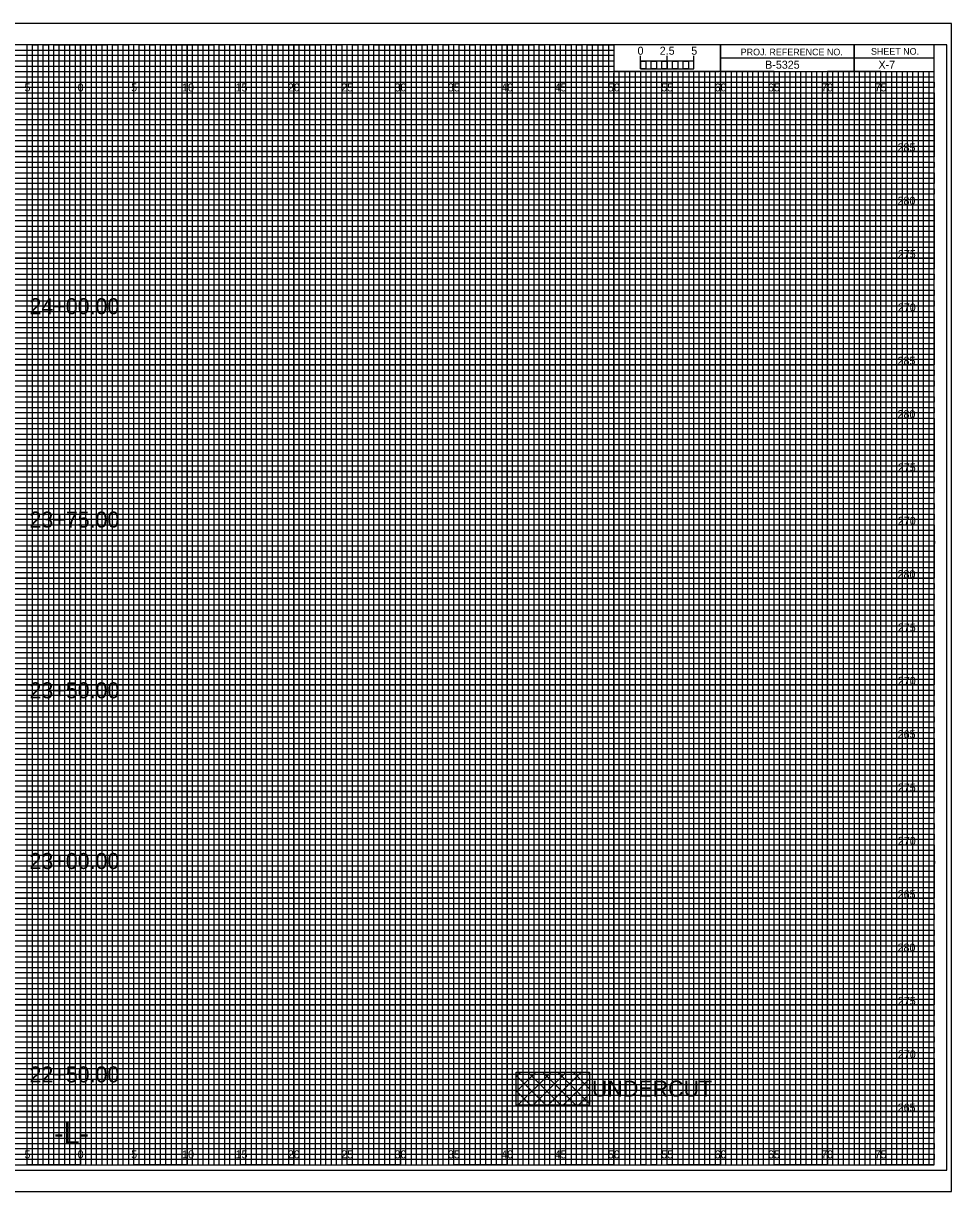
# Model space of a CAD drawing. Extents: x -7 to 162, y 658 to 767.
# Drawn here: x 74.6 to 161.7, y 657.5 to 767 of the extents above; entities that cross this region are included whole.
import ezdxf

# ---------------------------------------------------------------- set-up
doc = ezdxf.new("R2010")
doc.units = 0
for name, color, linetype in [('Default', 7, 'Continuous'), ('Prop XS Alignment Label', 7, 'Continuous'), ('Prop XS Bar Scale Labels', 7, 'Continuous'), ('Prop XS Elevation Labels', 7, 'Continuous'), ('Prop XS Offset Labels', 7, 'Continuous'), ('Prop XS Project Number', 7, 'Continuous'), ('Prop XS Sheet Number', 7, 'Continuous'), ('Prop XS Station Labels', 7, 'Continuous'), ('Sheet Cross Section CELL', 7, 'Continuous'), ('Sheet Cross Section Grid Major CELL', 7, 'Continuous'), ('Sheet Cross Section Grid Middle CELL', 7, 'Continuous'), ('Sheet Cross Section Grid Minor 1 CELL', 7, 'Continuous'), ('Sheet Cross Section Grid Minor 2 CELL', 7, 'Continuous'), ('Sheet Cross Section Scale CELL', 7, 'Continuous'), ('Sheet Cutting Line CELL', 7, 'Continuous'), ('Sheet DOT Grid CELL', 7, 'Continuous'), ('Sheet Plot Border Inside CELL', 7, 'Continuous'), ('Sheet Plot Border Outside CELL', 7, 'Continuous')]:
    doc.layers.add(name, color=color, linetype=linetype)

msp = doc.modelspace()

# ---------------------------------------------------------------- linework, layer by layer
at = {"layer": 'Default'}
for p, q in [((120.83, 668.27), (121.27, 668.7)), ((120.83, 666.85), (122.68, 668.7)), ((120.83, 668.37), (123.6, 665.6)), ((120.99, 665.6), (124.1, 668.7)), ((121.92, 668.7), (125.02, 665.6)), ((122.41, 665.6), (125.51, 668.7)), ((123.33, 668.7), (126.43, 665.6)), ((123.82, 665.6), (126.92, 668.7)), ((124.74, 668.7), (127.72, 665.72)), ((125.24, 665.6), (127.72, 668.08)), ((126.16, 668.7), (127.72, 667.14)), ((127.57, 668.7), (127.72, 668.55)), ((120.83, 666.96), (122.19, 665.6)), ((126.66, 665.6), (127.72, 666.67))]:
    msp.add_line(p, q, dxfattribs=at)
msp.add_lwpolyline([(120.83, 668.7), (127.72, 668.7), (127.72, 665.6), (120.83, 665.6)], close=True, dxfattribs=at)
at = {"layer": 'Sheet Cross Section CELL'}
for p, q in [((152.5, 765), (152.5, 762.5)), ((152.5, 762.5), (152.5, 765)), ((160, 763.75), (140, 763.75)), ((140, 763.75), (140, 762.5)), ((140, 762.5), (160, 762.5))]:
    msp.add_line(p, q, dxfattribs=at)
for points in [[(160, 765), (0, 765), (0, 660), (160, 660)], [(140, 765), (130, 765), (130, 762.51), (140, 762.51)], [(160, 765), (140, 765), (140, 762.5), (160, 762.5)]]:
    msp.add_lwpolyline(points, close=True, dxfattribs=at)
at = {"layer": 'Sheet Cross Section Grid Major CELL'}
for p, q in [((75, 765), (70, 765)), ((75, 660), (75, 765)), ((85, 765), (80, 765)), ((80, 765), (80, 660)), ((85, 660), (85, 765)), ((95, 765), (90, 765)), ((90, 765), (90, 660)), ((95, 660), (95, 765)), ((105, 765), (100, 765)), ((100, 765), (100, 660)), ((105, 660), (105, 765)), ((115, 765), (110, 765)), ((110, 765), (110, 660)), ((115, 660), (115, 765)), ((125, 765), (120, 765)), ((120, 765), (120, 660)), ((125, 660), (125, 765)), ((130, 765), (130, 660)), ((135, 660), (135, 762.5)), ((145, 762.5), (140, 762.5)), ((140, 762.5), (140, 660)), ((145, 660), (145, 762.5)), ((155, 762.5), (150, 762.5)), ((150, 762.5), (150, 660)), ((155, 660), (155, 762.5)), ((80, 660), (75, 660)), ((90, 660), (85, 660)), ((100, 660), (95, 660)), ((110, 660), (105, 660)), ((120, 660), (115, 660)), ((130, 660), (125, 660)), ((140, 660), (135, 660)), ((150, 660), (145, 660)), ((160, 660), (155, 660)), ((160, 660), (160, 660))]:
    msp.add_line(p, q, dxfattribs=at)
for points in [[(0, 760), (160, 760), (160, 755), (0, 755)], [(0, 750), (160, 750), (160, 745), (0, 745)], [(0, 740), (160, 740), (160, 735), (0, 735)], [(0, 730), (160, 730), (160, 725), (0, 725)], [(0, 720), (160, 720), (160, 715), (0, 715)], [(0, 710), (160, 710), (160, 705), (0, 705)], [(0, 700), (160, 700), (160, 695), (0, 695)], [(0, 690), (160, 690), (160, 685), (0, 685)], [(0, 680), (160, 680), (160, 675), (0, 675)], [(0, 670), (160, 670), (160, 665), (0, 665)]]:
    msp.add_lwpolyline(points, dxfattribs=at)
at = {"layer": 'Sheet Cross Section Grid Middle CELL'}
for points in [[(72.5, 660), (77.5, 660), (77.5, 765), (82.5, 765), (82.5, 660), (87.5, 660), (87.5, 765), (92.5, 765), (92.5, 660), (97.5, 660), (97.5, 765), (102.5, 765), (102.5, 660), (107.5, 660), (107.5, 765), (112.5, 765), (112.5, 660), (117.5, 660), (117.5, 765), (122.5, 765), (122.5, 660), (127.5, 660), (127.5, 765), (129.97, 765), (130, 765), (130, 762.5), (132.5, 762.5), (132.5, 660), (137.5, 660), (137.5, 762.5), (142.5, 762.5), (142.5, 660), (147.5, 660), (147.5, 762.5), (152.5, 762.5), (152.5, 660), (157.5, 660), (157.5, 762.5)], [(0, 762.5), (137.5, 762.5)], [(0, 752.5), (160, 752.5), (160, 757.5), (0, 757.5)], [(0, 742.5), (160, 742.5), (160, 747.5), (0, 747.5)], [(0, 732.5), (160, 732.5), (160, 737.5), (0, 737.5)], [(0, 722.5), (160, 722.5), (160, 727.5), (0, 727.5)], [(0, 712.5), (160, 712.5), (160, 717.5), (0, 717.5)], [(0, 702.5), (160, 702.5), (160, 707.5), (0, 707.5)], [(0, 692.5), (160, 692.5), (160, 697.5), (0, 697.5)], [(0, 682.5), (160, 682.5), (160, 687.5), (0, 687.5)], [(0, 672.5), (160, 672.5), (160, 677.5), (0, 677.5)], [(0, 662.5), (160, 662.5), (160, 667.5), (0, 667.5)]]:
    msp.add_lwpolyline(points, dxfattribs=at)
at = {"layer": 'Sheet Cross Section Grid Minor 1 CELL'}
for p, q in [((0, 764.5), (130, 764.5)), ((130, 764.5), (130, 763.99)), ((130, 763.99), (0, 763.99)), ((0, 763.5), (130, 763.5)), ((130, 763.5), (130, 762.95)), ((130, 762.95), (0, 762.95)), ((0, 762), (160, 762))]:
    msp.add_line(p, q, dxfattribs=at)
for points in [[(0, 761.5), (135, 761.5), (160, 761.5), (160, 761), (0, 761)], [(0, 760.5), (160, 760.5), (160, 759.5), (0, 759.5)], [(0, 759), (160, 759), (160, 758.5), (0, 758.49)], [(0, 758), (160, 758), (160, 757), (0, 757)], [(0, 756.5), (160, 756.5), (160, 756), (0, 756)], [(0, 755.5), (160, 755.5), (160, 754.5), (0, 754.5)], [(0, 754), (160, 754), (160, 753.5), (0, 753.5)], [(0, 753), (160, 753), (160, 752), (0, 752)], [(0, 751.5), (160, 751.5), (160, 751), (0, 751)], [(0, 750.5), (160, 750.5), (160, 749.5), (0, 749.5)], [(0, 749), (160, 749), (160, 748.5), (0, 748.5)], [(0, 748), (160, 748), (160, 746.98), (160, 746.5), (160, 746), (0, 746)], [(0, 747), (160, 747), (160, 746.5), (0, 746.5)], [(0, 745.5), (160, 745.5), (160, 744.5), (0, 744.51)], [(0, 744.51), (160, 744.5), (160, 744), (0, 744)], [(0, 743.5), (160, 743.5), (160, 743), (0, 743)], [(0, 742), (160, 742), (160, 741.5), (0, 741.5)], [(0, 741), (160, 741), (160, 740.5), (0, 740.5)], [(-0.04, 739.45), (160, 739.45), (160, 738.94), (-0.04, 738.94)], [(0, 738.5), (160, 738.5), (160, 738), (0, 738)], [(0, 737), (160, 737), (160, 736.5), (0, 736.5)], [(0, 736), (160, 736), (160, 735.5), (0, 735.5)], [(0, 734.5), (160, 734.5), (160, 734), (0, 734)], [(0, 733.5), (160, 733.5), (160, 733), (0, 733)], [(0, 732), (160, 732), (160, 731.5), (0, 731.5)], [(0, 731), (160, 731), (160, 730.5), (0, 730.5)], [(0, 729.5), (160, 729.5), (160, 728.99), (0, 729)], [(0, 728.5), (160, 728.5), (160, 728), (0, 728)], [(0, 727), (160, 727), (160, 726.5), (0, 726.5)], [(0, 726), (160, 726), (160, 725.5), (0, 725.5)], [(0, 724.5), (160, 724.5), (160, 724), (0, 724)], [(0, 723.5), (160, 723.5), (160, 723), (0, 723)], [(0, 722), (160, 722), (160, 721.5), (0, 721.5)], [(0, 721), (160, 721), (160, 720.5), (0, 720.5)], [(0, 719.5), (160, 719.5), (160, 719), (0, 719)], [(0, 718.5), (160.03, 718.46), (160, 718), (0, 718)], [(0, 717), (160, 717), (160, 716.5), (0, 716.5)], [(0, 716), (160, 716), (160, 715.5), (0, 715.5)], [(0, 714.5), (160, 714.5), (160, 714), (0, 714)], [(0, 713.5), (160, 713.5), (160, 713), (0, 713)], [(0, 712), (160, 712), (160, 711.5), (0, 711.5)], [(0, 711), (160, 711), (160, 710.5), (0, 710.5)], [(0, 709.5), (160, 709.5), (160, 709), (0, 709)], [(0, 708.5), (160, 708.5), (160, 708), (0, 708)], [(0, 707), (160, 707), (160, 706.5), (0, 706.5)], [(0, 706), (160, 706), (160, 705.5), (0, 705.5)], [(0, 704.5), (160, 704.5), (160, 704), (0, 704)], [(0, 703.5), (160, 703.5), (160, 703), (0, 703)], [(0, 702), (160, 702), (160, 701.5), (0, 701.5)], [(0, 701), (160, 701), (160, 700.5), (0, 700.5)], [(0, 699.5), (160, 699.5), (160, 698.99), (0, 699)], [(0, 698.5), (160, 698.5), (160, 698), (0, 698)], [(0, 697), (160, 697), (160, 696.5), (0, 696.5)], [(0, 696), (160, 696), (160, 695.5), (0, 695.5)], [(0, 694.5), (160, 694.5), (160, 694), (0, 694)], [(0, 693.5), (160, 693.5), (160, 693), (0, 693)], [(0, 692), (160, 692), (160, 691.5), (0, 691.5)], [(0, 691), (160, 691), (160, 690.5), (0, 690.5)], [(0, 689.5), (160, 689.5), (160, 689), (0, 689)], [(0, 688.5), (160.03, 688.46), (160, 688), (0, 688)], [(0, 687), (160, 687), (160, 686.5), (0, 686.5)], [(0, 686), (160, 686), (160, 685.5), (0, 685.5)], [(0, 684.5), (160, 684.5), (160, 684), (0, 684)], [(0, 683.5), (160, 683.5), (160, 683), (0, 683)], [(0, 682), (160, 682), (160, 681.5), (0, 681.5)], [(0, 681), (160, 681), (160, 680.5), (0, 680.5)], [(0, 679.5), (160, 679.5), (160, 679), (0, 679)], [(0, 678.5), (160, 678.5), (160, 678), (0, 678)], [(0, 677), (160, 677), (160, 676.5), (0, 676.5)], [(0, 676), (160, 676), (160, 675.5), (0, 675.5)], [(0, 674.5), (160, 674.5), (160, 674), (0, 674)], [(0, 673.5), (160, 673.5), (160, 673), (0, 673)], [(0, 672), (160, 672), (160, 671.5), (0, 671.5)], [(0, 671), (160, 671), (160, 670.5), (0, 670.5)], [(0, 669.5), (160, 669.5), (160, 669), (0, 669)], [(0, 668.5), (160, 668.5), (160, 668), (0, 668)], [(0, 667), (160, 667), (160, 666.5), (0, 666.5)], [(0, 666), (160, 666), (160, 665.5), (0, 665.5)], [(0, 664.5), (160, 664.5), (160, 664), (0, 664)], [(0, 663.5), (160, 663.5), (160, 663), (0, 663)], [(0, 662), (160, 662), (160, 661.5), (0, 661.5)], [(0, 661), (160, 661), (160, 660.5), (0, 660.5)]]:
    msp.add_lwpolyline(points, dxfattribs=at)
at = {"layer": 'Sheet Cross Section Grid Minor 2 CELL'}
for p, q in [((133.5, 762.5), (133, 762.5)), ((133, 762.5), (133, 660)), ((133.5, 660), (133.5, 762.5)), ((134.5, 762.5), (134, 762.5)), ((134, 762.5), (134, 660)), ((134.5, 660), (134.5, 762.5)), ((133, 660), (132.5, 660)), ((134, 660), (133.5, 660))]:
    msp.add_line(p, q, dxfattribs=at)
for points in [[(75, 660), (75.5, 660), (75.5, 765), (76, 765), (76, 660)], [(76, 660), (76.5, 660), (76.5, 765), (77, 765), (77, 660)], [(77.5, 660), (78, 660), (78, 765), (78.5, 765), (78.5, 660)], [(78.5, 660), (79, 660), (79, 765), (79.5, 765), (79.5, 660)], [(80, 660), (80.5, 660), (80.5, 765), (81, 765), (81, 660)], [(81, 660), (81.5, 660), (81.5, 765), (82, 765), (82, 660)], [(82.5, 660), (83, 660), (83, 765), (83.5, 765), (83.5, 660)], [(83.5, 660), (84, 660), (84, 765), (84.5, 765), (84.5, 660)], [(85, 660), (85.5, 660), (85.5, 765), (86, 765), (86, 660)], [(86, 660), (86.5, 660), (86.5, 765), (87, 765), (87, 660)], [(87.5, 660), (88, 660), (88, 765), (88.5, 765), (88.5, 660)], [(88.5, 660), (89, 660), (89, 765), (89.5, 765), (89.5, 660)], [(90, 660), (90.5, 660), (90.5, 765), (91, 765), (91, 660)], [(91, 660), (91.5, 660), (91.5, 765), (92, 765), (92, 660)], [(92.5, 660), (93, 660), (93, 765), (93.5, 765), (93.5, 660)], [(93.5, 660), (94, 660), (94, 765), (94.5, 765), (94.5, 660)], [(95, 660), (95.5, 660), (95.5, 765), (96, 765), (96, 660)], [(96, 660), (96.5, 660), (96.5, 765), (97, 765), (97, 660)], [(97.5, 660), (98, 660), (98, 765), (98.5, 765), (98.5, 660)], [(98.5, 660), (99, 660), (99, 765), (99.5, 765), (99.5, 660)], [(100, 660), (100.5, 660), (100.5, 765), (101, 765), (101, 660)], [(101, 660), (101.5, 660), (101.5, 765), (102, 765), (102, 660)], [(102.5, 660), (103, 660), (103, 765), (103.5, 765), (103.5, 660)], [(103.5, 660), (104, 660), (104, 765), (104.5, 765), (104.5, 660)], [(105, 660), (105.5, 660), (105.5, 765), (106, 765), (106, 660)], [(106, 660), (106.5, 660), (106.5, 765), (107, 765), (107, 660)], [(107.5, 660), (108, 660), (108, 765), (108.5, 765), (108.5, 660)], [(108.5, 660), (109, 660), (109, 765), (109.5, 765), (109.5, 660)], [(110, 660), (110.5, 660), (110.5, 765), (111, 765), (111, 660)], [(111, 660), (111.5, 660), (111.5, 765), (112, 765), (112, 660)], [(112.5, 660), (113, 660), (113, 765), (113.5, 765), (113.5, 660)], [(113.5, 660), (114, 660), (114, 765), (114.5, 765), (114.5, 660)], [(115, 660), (115.5, 660), (115.5, 765), (116, 765), (116, 660)], [(116, 660), (116.5, 660), (116.5, 765), (117, 765), (117, 660)], [(117.5, 660), (118, 660), (118, 765), (118.5, 765), (118.5, 660)], [(118.5, 660), (119, 660), (119, 765), (119.5, 765), (119.5, 660)], [(120, 660), (120.5, 660), (120.5, 765), (121, 765), (121, 660)], [(121, 660), (121.5, 660), (121.5, 765), (122, 765), (122, 660)], [(122.5, 660), (123, 660), (123, 765), (123.5, 765), (123.5, 660)], [(123.5, 660), (124, 660), (124, 765), (124.5, 765), (124.5, 660)], [(125, 660), (125.5, 660), (125.5, 765), (126, 765), (126, 660)], [(126, 660), (126.5, 660), (126.5, 765), (127, 765), (127, 660)], [(127.5, 660), (128, 660), (128, 765), (128.5, 765), (128.5, 660)], [(128.5, 660), (129, 660), (129, 765), (129.5, 765), (129.5, 660)], [(130, 660), (130.5, 660), (130.5, 762.5), (131.01, 762.5), (131.01, 660)], [(131, 660), (131.5, 660), (131.5, 762.5), (132, 762.5), (132, 660)], [(135, 660), (135.49, 660), (135.49, 762.5), (136, 762.5), (136, 660)], [(136, 660), (136.5, 660), (136.5, 762.5), (137.03, 762.5), (137.03, 660)], [(137.5, 660), (138, 660), (138, 762.5), (138.5, 762.5), (138.5, 660)], [(138.5, 660), (139, 660), (139, 762.5), (139.5, 762.5), (139.5, 660)], [(140, 660), (140.5, 660), (140.5, 762.5), (141, 762.5), (141, 660)], [(141, 660), (141.5, 660), (141.5, 762.5), (142, 762.5), (142, 660)], [(142.5, 660), (143, 660), (143, 762.5), (143.5, 762.5), (143.5, 660)], [(143.5, 660), (144, 660), (144, 762.5), (144.5, 762.5), (144.5, 660)], [(145, 660), (145.5, 660), (145.5, 762.5), (146, 762.5), (146, 660)], [(146, 660), (146.5, 660), (146.5, 762.5), (147, 762.5), (147, 660)], [(147.5, 660), (148, 660), (148, 762.5), (148.5, 762.5), (148.5, 660)], [(148.5, 660), (149, 660), (149, 762.5), (149.5, 762.5), (149.5, 660)], [(150, 660), (150.5, 660), (150.5, 762.5), (151, 762.5), (151, 660)], [(151, 660), (151.5, 660), (151.5, 762.5), (152, 762.5), (152, 660)], [(152.5, 660), (153, 660), (153, 762.5), (153.5, 762.5), (153.5, 660)], [(153.5, 660), (154, 660), (154, 762.5), (154.5, 762.5), (154.5, 660)], [(155, 660), (155.5, 660), (155.5, 762.5), (156, 762.5), (156, 660)], [(156, 660), (156.5, 660), (156.5, 762.5), (157, 762.5), (157, 660)], [(157.5, 660), (158, 660), (158, 762.5), (158.5, 762.5), (158.5, 660)], [(158.5, 660), (159, 660), (159, 762.5), (159.5, 762.5), (159.5, 660)]]:
    msp.add_lwpolyline(points, dxfattribs=at)
at = {"layer": 'Sheet Cross Section Scale CELL'}
for p, q in [((132.5, 762.75), (132.5, 763.95)), ((132.5, 763.45), (132.5, 763.95)), ((135, 762.75), (135, 763.95)), ((137.5, 762.75), (137.5, 763.95)), ((137.5, 763.45), (137.5, 763.95))]:
    msp.add_line(p, q, dxfattribs=at)
for points in [[(137.5, 763.45), (132.5, 763.45), (132.5, 762.75), (137.5, 762.75)], [(132.5, 763.45), (133, 763.45), (133, 762.75), (132.5, 762.75)], [(133.5, 763.45), (134, 763.45), (134, 762.75), (133.5, 762.75)], [(134.5, 763.45), (135, 763.45), (135, 762.75), (134.5, 762.75)], [(135.5, 763.45), (136, 763.45), (136, 762.75), (135.5, 762.75)], [(136.5, 763.45), (137, 763.45), (137, 762.75), (136.5, 762.75)]]:
    msp.add_lwpolyline(points, close=True, dxfattribs=at)
at = {"layer": 'Sheet Cutting Line CELL'}
for p, q in [((161.65, 767), (-6.7, 767)), ((-6.7, 657.5), (161.65, 657.5))]:
    msp.add_line(p, q, dxfattribs=at)
at = {"layer": 'Sheet DOT Grid CELL'}
for p, q in [((75, 660), (75, 765)), ((80, 660), (80, 765)), ((85, 660), (85, 765)), ((90, 660), (90, 765)), ((95, 660), (95, 765)), ((100, 660), (100, 765)), ((105, 660), (105, 765)), ((110, 660), (110, 765)), ((115, 660), (115, 765)), ((120, 660), (120, 765)), ((125, 660), (125, 765)), ((130, 660), (130, 762.34)), ((135, 660), (135, 762.34)), ((140, 660), (140, 762.34)), ((145, 660), (145, 762.34)), ((150, 660), (150, 762.34)), ((155, 660), (155, 762.34)), ((0, 760), (160, 760)), ((0, 755), (160, 755)), ((0, 750), (160, 750)), ((0, 745), (160, 745)), ((0, 740), (160, 740)), ((0, 735), (160, 735)), ((0, 730), (160, 730)), ((0, 725), (160, 725)), ((0, 720), (160, 720)), ((0, 715), (160, 715)), ((0, 710), (160, 710)), ((0, 705), (160, 705)), ((0, 700), (160, 700)), ((0, 695), (160, 695)), ((0, 690), (160, 690)), ((0, 685), (160, 685)), ((0, 680), (160, 680)), ((0, 675), (160, 675)), ((0, 670), (160, 670)), ((0, 665), (160, 665))]:
    msp.add_line(p, q, dxfattribs=at)
at = {"layer": 'Sheet Plot Border Inside CELL'}
msp.add_lwpolyline([(-5.4, 659.5), (161.2, 659.5), (161.2, 765), (-5.4, 765)], close=True, dxfattribs=at)
at = {"layer": 'Sheet Plot Border Outside CELL'}
msp.add_lwpolyline([(-6.7, 657.5), (161.65, 657.5), (161.65, 767), (-6.7, 767)], close=True, dxfattribs=at)

# ---------------------------------------------------------------- texts
at = {"layer": 'Default'}
msp.add_text('UNDERCUT', height=1.5, dxfattribs=at).set_placement((127.94, 666.41))
at = {"layer": 'Prop XS Alignment Label'}
msp.add_text('-L-', height=2, dxfattribs=at).set_placement((77.53, 662))
at = {"layer": 'Prop XS Bar Scale Labels'}
for s, p in [('2.5', (134.29, 764.06)), ('5', (137.24, 764.06))]:
    msp.add_text(s, height=0.75, dxfattribs=at).set_placement(p)
at = {"layer": 'Prop XS Elevation Labels'}
for s, p in [('285', (156.58, 755)), ('280', (156.58, 750)), ('275', (156.61, 745)), ('270', (156.61, 740)), ('285', (156.58, 735)), ('280', (156.58, 730)), ('275', (156.61, 725)), ('270', (156.61, 720)), ('280', (156.58, 715)), ('275', (156.61, 710)), ('270', (156.61, 705)), ('265', (156.59, 700)), ('275', (156.61, 695)), ('270', (156.61, 690)), ('265', (156.59, 685)), ('280', (156.58, 680)), ('275', (156.61, 675)), ('270', (156.61, 670)), ('265', (156.59, 665))]:
    msp.add_text(s, height=0.75, dxfattribs=at).set_placement(p)
at = {"layer": 'Prop XS Offset Labels'}
for s, p in [('5', (74.74, 760.62)), ('0', (79.73, 760.62)), ('0', (79.73, 760.62)), ('5', (84.74, 760.62)), ('10', (89.52, 760.62)), ('15', (94.53, 760.62)), ('20', (99.43, 760.62)), ('25', (104.44, 760.62)), ('30', (109.43, 760.62)), ('35', (114.44, 760.62)), ('40', (119.43, 760.62)), ('45', (124.44, 760.62)), ('50', (129.43, 760.62)), ('55', (134.44, 760.62)), ('60', (139.43, 760.62)), ('65', (144.44, 760.62)), ('70', (149.43, 760.62)), ('75', (154.44, 760.62)), ('0', (79.73, 660.62)), ('0', (79.73, 660.62)), ('10', (89.52, 660.62)), ('20', (99.43, 660.62)), ('25', (104.44, 660.62)), ('30', (109.43, 660.62)), ('35', (114.44, 660.62)), ('40', (119.43, 660.62)), ('50', (129.43, 660.62)), ('60', (139.43, 660.62)), ('65', (144.44, 660.62)), ('70', (149.43, 660.62)), ('5', (74.74, 660.62)), ('5', (84.74, 660.62)), ('15', (94.53, 660.62)), ('45', (124.44, 660.62)), ('55', (134.44, 660.62)), ('75', (154.44, 660.62))]:
    msp.add_text(s, height=0.75, dxfattribs=at).set_placement(p)
at = {"layer": 'Prop XS Project Number'}
msp.add_text('B-5325', height=0.75, dxfattribs=at).set_placement((144.17, 762.75))
at = {"layer": 'Prop XS Sheet Number'}
msp.add_text('X-7', height=0.75, dxfattribs=at).set_placement((154.79, 762.75))
at = {"layer": 'Prop XS Station Labels'}
for s, p in [('24+00.00', (75.21, 739.74)), ('23+75.00', (75.21, 719.74)), ('23+50.00', (75.21, 703.74)), ('23+00.00', (75.21, 687.74)), ('22+50.00', (75.21, 667.74))]:
    msp.add_text(s, height=1.5, dxfattribs=at).set_placement(p)
at = {"layer": 'Sheet Cross Section CELL'}
for s, p in [('PROJ. REFERENCE NO.', (141.88, 764)), ('SHEET NO.', (154.09, 764.06))]:
    msp.add_text(s, height=0.625, dxfattribs=at).set_placement(p)
at = {"layer": 'Sheet Cross Section Scale CELL'}
msp.add_text('0', height=0.75, dxfattribs=at).set_placement((132.21, 764.06))

doc.saveas('drawing.dxf')
